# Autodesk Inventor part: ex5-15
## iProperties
Shininess: 64.0
Length Units: 11272
Angle Units: 11279
Time Units: 11290
Mass Units: 11286
Length Display Precision: 3
Angle Display Precision: 2
Compacted: True
Part Number: ex5-15
Document SubType Name: Modeling
Created: 2003-11
Designer: Elise Moss
Cost Center: 0.1 lbmass
Authority: 1.91 in^3
Manufacturer: Standard
Standards Organization: Custom
Density: 0.0
Volumn: 0.0
Area: 0.0
PropertySet Name: Model Information
Control State: 0
Master: False
Checked Out: False
SaveDate: 2003-11-14
SaveTime: 21:17
TotalMass: 0.1 lbmass
TotalVolume: 1.91 in^3
Author: Elise Moss
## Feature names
1. Loft1
2. Shell1
3. Extrusion1
4. Sweep1
5. Extrusion2
6. Coil1
7. Fillet1
8. Fillet2
9. FaceDraft1
